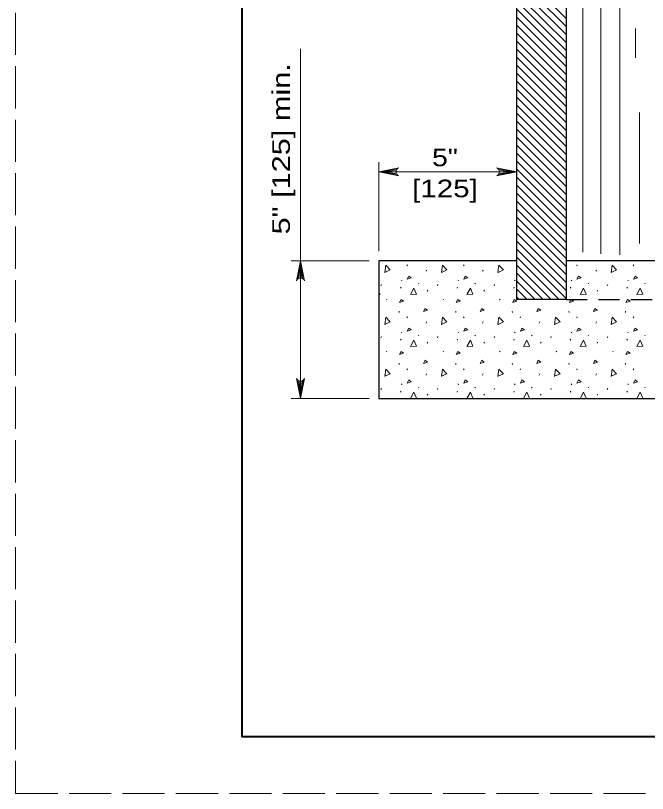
# Model space of a CAD drawing. Extents: x 1302.9 to 1336.9, y 688.5 to 710.5.
# Drawn here: x 1302.88 to 1308.46, y 688.5 to 695.37 of the extents above; entities that cross this region are included whole.
import ezdxf
from ezdxf.enums import TextEntityAlignment as Align

# ---------------------------------------------------------------- set-up
doc = ezdxf.new("R2010")
doc.units = 0
doc.header["$LTSCALE"] = 0.062
doc.linetypes.add('LONG_DASHED', pattern=[7.5, 6, -1.5])
doc.linetypes.add('MEDIUM_DASHED', pattern=[4.5, 3, -1.5])
doc.layers.add('1', color=7, linetype='Continuous', lineweight=13)

msp = doc.modelspace()

# ---------------------------------------------------------------- linework, layer by layer
at = {"layer": '1', "lineweight": 25}
for p, q in [((1307.30208, 692.86483), (1307.30208, 698.95525)), ((1312.14367, 693.20833), (1307.73933, 693.20833))]:
    msp.add_line(p, q, dxfattribs=at)
at = {"layer": '1'}
for p, q in [((1308.21275, 697.65342), (1308.21275, 693.26017)), ((1308.04517, 696.20892), (1308.04517, 693.26933)), ((1307.88642, 693.28483), (1307.88642, 696.11992)), ((1307.73933, 695.34767), (1307.30208, 695.78492)), ((1307.73933, 695.277), (1307.30208, 695.71425)), ((1307.73933, 695.20633), (1307.30208, 695.64358)), ((1307.73933, 695.13567), (1307.30208, 695.57292)), ((1307.73933, 695.065), (1307.30208, 695.50225)), ((1307.73933, 694.99433), (1307.30208, 695.43158)), ((1307.73933, 694.92358), (1307.30208, 695.36083)), ((1307.73933, 694.853), (1307.30208, 695.29025)), ((1307.73933, 694.78225), (1307.30208, 695.2195)), ((1308.3505, 694.9995), (1308.3505, 695.25892)), ((1307.73933, 694.71167), (1307.30208, 695.14892)), ((1305.39242, 691.99033), (1305.39242, 695.07867)), ((1307.73933, 694.64092), (1307.30208, 695.07817)), ((1307.73933, 694.57033), (1307.30208, 695.00758)), ((1307.73933, 694.49958), (1307.30208, 694.93683)), ((1307.73933, 694.429), (1307.30208, 694.86625)), ((1307.73933, 694.35825), (1307.30208, 694.7955)), ((1307.73933, 694.28767), (1307.30208, 694.72492)), ((1307.73933, 694.21692), (1307.30208, 694.65417)), ((1307.73933, 694.14633), (1307.30208, 694.58358)), ((1307.73933, 694.07558), (1307.30208, 694.51283)), ((1308.38742, 694.51717), (1308.38742, 693.36158)), ((1307.73933, 694.005), (1307.30208, 694.44225)), ((1307.73933, 693.93425), (1307.30208, 694.3715)), ((1307.30208, 693.5255), (1307.30208, 694.31167)), ((1307.73933, 693.86367), (1307.30208, 694.30092)), ((1307.73933, 693.79292), (1307.30208, 694.23017)), ((1307.73933, 693.72225), (1307.30208, 694.1595)), ((1306.08392, 693.29167), (1306.08392, 694.07775)), ((1307.73933, 693.65158), (1307.30208, 694.08883)), ((1306.24417, 694.01692), (1306.08392, 693.9945)), ((1306.23875, 694.00583), (1306.08392, 693.9945)), ((1307.30208, 693.9945), (1306.08392, 693.9945)), ((1306.23708, 693.9945), (1306.08392, 693.9945)), ((1306.23992, 693.98008), (1306.08392, 693.9945)), ((1306.246, 693.96967), (1306.08392, 693.9945)), ((1307.13992, 693.96967), (1307.30208, 693.9945)), ((1307.14183, 694.01692), (1307.30208, 693.9945)), ((1307.14608, 693.98008), (1307.30208, 693.9945)), ((1307.14725, 694.00583), (1307.30208, 693.9945)), ((1307.14892, 693.9945), (1307.30208, 693.9945)), ((1307.73933, 693.58092), (1307.30208, 694.01817)), ((1307.73933, 693.51025), (1307.30208, 693.9475)), ((1307.73933, 693.43958), (1307.30208, 693.87683)), ((1307.73933, 693.36892), (1307.30208, 693.80617)), ((1307.73933, 693.29825), (1307.30208, 693.7355)), ((1307.73933, 693.22758), (1307.30208, 693.66483)), ((1307.73933, 693.15692), (1307.30208, 693.59417)), ((1307.73933, 693.08625), (1307.30208, 693.5235)), ((1307.73933, 693.01558), (1307.30208, 693.45283)), ((1307.73933, 692.94492), (1307.30208, 693.38217)), ((1307.73933, 692.87425), (1307.30208, 693.3115)), ((1307.67817, 692.86483), (1307.30208, 693.24083)), ((1306.00058, 693.20833), (1305.30908, 693.20833)), ((1305.36758, 693.04625), (1305.39242, 693.20833)), ((1305.378, 693.05233), (1305.39242, 693.20833)), ((1305.39242, 693.05517), (1305.39242, 693.20833)), ((1305.40375, 693.0535), (1305.39242, 693.20833)), ((1305.41483, 693.04808), (1305.39242, 693.20833)), ((1306.33317, 693.16158), (1306.33758, 693.17158)), ((1306.833, 693.16158), (1306.83742, 693.17158)), ((1307.60742, 692.86483), (1307.30208, 693.17017)), ((1307.8325, 693.16158), (1307.83692, 693.17158)), ((1308.33225, 693.16158), (1308.33667, 693.17158)), ((1306.50175, 693.11608), (1306.50625, 693.12608)), ((1307.00158, 693.11608), (1307.00608, 693.12608)), ((1307.53683, 692.86483), (1307.30208, 693.0995)), ((1308.00108, 693.11608), (1308.00558, 693.12608)), ((1306.2845, 693.03733), (1306.289, 693.03075)), ((1306.78425, 693.03733), (1306.78875, 693.03075)), ((1307.284, 693.03733), (1307.2885, 693.03075)), ((1307.46608, 692.86483), (1307.30208, 693.02883)), ((1307.78375, 693.03733), (1307.78825, 693.03075)), ((1308.2835, 693.03733), (1308.288, 693.03075)), ((1306.10308, 692.98742), (1306.1075, 692.99742)), ((1306.27617, 692.96425), (1306.28058, 692.97425)), ((1306.434, 693.00917), (1306.43842, 693.0025)), ((1306.60283, 692.98742), (1306.60725, 692.99742)), ((1306.77592, 692.96425), (1306.78033, 692.97425)), ((1306.93375, 693.00917), (1306.93817, 693.0025)), ((1307.10258, 692.98742), (1307.107, 692.99742)), ((1307.27567, 692.96425), (1307.28008, 692.97425)), ((1307.39533, 692.86483), (1307.30208, 692.95808)), ((1307.77542, 692.96425), (1307.77983, 692.97425)), ((1307.93325, 693.00917), (1307.93767, 693.0025)), ((1308.10208, 692.98742), (1308.1065, 692.99742)), ((1308.27517, 692.96425), (1308.27958, 692.97425)), ((1308.43308, 693.00917), (1308.43742, 693.0025)), ((1306.09525, 692.90842), (1306.08392, 692.91)), ((1306.51292, 692.93875), (1306.51733, 692.94867)), ((1307.01275, 692.93875), (1307.01717, 692.94867)), ((1307.32475, 692.86483), (1307.30208, 692.8875)), ((1308.01225, 692.93875), (1308.01667, 692.94867)), ((1306.15183, 692.86775), (1306.15625, 692.86108)), ((1306.65167, 692.86775), (1306.65608, 692.86108)), ((1307.15142, 692.86775), (1307.15583, 692.86108)), ((1308.15092, 692.86775), (1308.15533, 692.86108)), ((1306.264, 692.76125), (1306.26517, 692.75125)), ((1306.76375, 692.76125), (1306.76492, 692.75125)), ((1307.2635, 692.76125), (1307.26467, 692.75125)), ((1307.76325, 692.76125), (1307.76442, 692.75125)), ((1308.263, 692.76125), (1308.26417, 692.75125)), ((1306.33317, 692.70242), (1306.33758, 692.71242)), ((1306.833, 692.70242), (1306.83742, 692.71242)), ((1307.33275, 692.70242), (1307.33717, 692.71242)), ((1307.8325, 692.70242), (1307.83692, 692.71242)), ((1308.33225, 692.70242), (1308.33667, 692.71242)), ((1306.50175, 692.65692), (1306.50625, 692.66692)), ((1307.00158, 692.65692), (1307.00608, 692.66692)), ((1307.50133, 692.65692), (1307.50583, 692.66692)), ((1308.00108, 692.65692), (1308.00558, 692.66692)), ((1306.10308, 692.52825), (1306.1075, 692.53825)), ((1306.2845, 692.57825), (1306.289, 692.57158)), ((1306.434, 692.55), (1306.43842, 692.54333)), ((1306.60283, 692.52825), (1306.60725, 692.53825)), ((1306.78425, 692.57825), (1306.78875, 692.57158)), ((1306.93375, 692.55), (1306.93817, 692.54333)), ((1307.10258, 692.52825), (1307.107, 692.53825)), ((1307.284, 692.57825), (1307.2885, 692.57158)), ((1307.4335, 692.55), (1307.43792, 692.54333)), ((1307.60233, 692.52825), (1307.60675, 692.53825)), ((1307.78375, 692.57825), (1307.78825, 692.57158)), ((1307.93325, 692.55), (1307.93767, 692.54333)), ((1308.10208, 692.52825), (1308.1065, 692.53825)), ((1308.2835, 692.57825), (1308.288, 692.57158)), ((1308.43308, 692.55), (1308.43742, 692.54333)), ((1306.27617, 692.50508), (1306.28058, 692.51508)), ((1306.51292, 692.47958), (1306.51733, 692.4895)), ((1306.77592, 692.50508), (1306.78033, 692.51508)), ((1307.01275, 692.47958), (1307.01717, 692.4895)), ((1307.27567, 692.50508), (1307.28008, 692.51508)), ((1307.5125, 692.47958), (1307.51692, 692.4895)), ((1307.77542, 692.50508), (1307.77983, 692.51508)), ((1308.01225, 692.47958), (1308.01667, 692.4895)), ((1308.27517, 692.50508), (1308.27958, 692.51508)), ((1306.15183, 692.40858), (1306.15625, 692.40192)), ((1306.65167, 692.40858), (1306.65608, 692.40192)), ((1307.15142, 692.40858), (1307.15583, 692.40192)), ((1307.65117, 692.40858), (1307.65558, 692.40192)), ((1308.15092, 692.40858), (1308.15533, 692.40192)), ((1306.264, 692.30217), (1306.26517, 692.29217)), ((1306.76375, 692.30217), (1306.76492, 692.29217)), ((1307.2635, 692.30217), (1307.26467, 692.29217)), ((1307.76325, 692.30217), (1307.76442, 692.29217)), ((1308.263, 692.30217), (1308.26417, 692.29217)), ((1306.33317, 692.24325), (1306.33758, 692.25325)), ((1306.50175, 692.19775), (1306.50625, 692.20775)), ((1306.833, 692.24325), (1306.83742, 692.25325)), ((1307.00158, 692.19775), (1307.00608, 692.20775)), ((1307.33275, 692.24325), (1307.33717, 692.25325)), ((1307.50133, 692.19775), (1307.50583, 692.20775)), ((1307.8325, 692.24325), (1307.83692, 692.25325)), ((1308.00108, 692.19775), (1308.00558, 692.20775)), ((1308.33225, 692.24325), (1308.33667, 692.25325)), ((1305.37, 692.15058), (1305.39242, 691.99033)), ((1305.38108, 692.14508), (1305.39242, 691.99033)), ((1305.41717, 692.15242), (1305.39242, 691.99033)), ((1305.40675, 692.14633), (1305.39242, 691.99033)), ((1305.39242, 692.1435), (1305.39242, 691.99033)), ((1306.10308, 692.06908), (1306.1075, 692.07908)), ((1306.2845, 692.11908), (1306.289, 692.11242)), ((1306.434, 692.09083), (1306.43842, 692.08417)), ((1306.60283, 692.06908), (1306.60725, 692.07908)), ((1306.78425, 692.11908), (1306.78875, 692.11242)), ((1306.93375, 692.09083), (1306.93817, 692.08417)), ((1307.10258, 692.06908), (1307.107, 692.07908)), ((1307.284, 692.11908), (1307.2885, 692.11242)), ((1307.4335, 692.09083), (1307.43792, 692.08417)), ((1307.60233, 692.06908), (1307.60675, 692.07908)), ((1307.78375, 692.11908), (1307.78825, 692.11242)), ((1307.93325, 692.09083), (1307.93767, 692.08417)), ((1308.10208, 692.06908), (1308.1065, 692.07908)), ((1308.2835, 692.11908), (1308.288, 692.11242)), ((1308.43308, 692.09083), (1308.43742, 692.08417)), ((1306.00058, 691.99033), (1305.30908, 691.99033)), ((1306.27617, 692.04592), (1306.28058, 692.05592)), ((1306.51292, 692.02042), (1306.51733, 692.03033)), ((1306.77592, 692.04592), (1306.78033, 692.05592)), ((1307.01275, 692.02042), (1307.01717, 692.03033)), ((1307.27567, 692.04592), (1307.28008, 692.05592)), ((1307.5125, 692.02042), (1307.51692, 692.03033)), ((1307.77542, 692.04592), (1307.77983, 692.05592)), ((1308.01225, 692.02042), (1308.01667, 692.03033)), ((1308.27517, 692.04592), (1308.27958, 692.05592))]:
    msp.add_line(p, q, dxfattribs=at)
at = {"layer": '1', "linetype": 'MEDIUM_DASHED', "lineweight": 25}
msp.add_line((1307.73933, 692.86483), (1312.14367, 692.86483), dxfattribs=at)
at = {"layer": '1', "linetype": 'LONG_DASHED'}
msp.add_lwpolyline([(1302.8765, 688.50158), (1336.8765, 688.50158), (1336.8765, 710.50158), (1302.8765, 710.50158)], close=True, dxfattribs=at)
at = {"layer": '1', "lineweight": 25}
for points in [[(1336.3765, 689.00158), (1304.8765, 689.00158), (1304.8765, 710.00158)], [(1307.73933, 700.04825), (1307.73933, 692.86483), (1307.30208, 692.86483)], [(1306.08392, 691.99033), (1313.799, 691.99033), (1313.799, 693.20833), (1312.58092, 693.20833)], [(1307.30208, 693.20833), (1306.08392, 693.20833), (1306.08392, 691.99033)]]:
    msp.add_lwpolyline(points, dxfattribs=at)
at = {"layer": '1', "lineweight": 40}
msp.add_lwpolyline([(1304.8765, 710.00158), (1336.3765, 710.00158), (1336.3765, 689.00158), (1304.8765, 689.00158)], close=True, dxfattribs=at)
msp.add_lwpolyline([(1304.8765, 710.00158), (1336.3765, 710.00158), (1336.3765, 689.00158), (1304.8765, 689.00158)], close=True, dxfattribs=at)
at = {"layer": '1'}
for points in [[(1306.26092, 693.95908), (1306.08392, 693.9945), (1306.26092, 694.02992)], [(1307.12508, 693.95908), (1307.30208, 693.9945), (1307.12508, 694.02992)], [(1305.357, 693.03133), (1305.39242, 693.20833), (1305.42783, 693.03133)], [(1306.137, 693.10458), (1306.14583, 693.16808), (1306.18558, 693.127), (1306.13808, 693.105)], [(1306.63683, 693.10458), (1306.64567, 693.16808), (1306.68533, 693.127), (1306.63783, 693.105)], [(1307.13658, 693.10458), (1307.14542, 693.16808), (1307.18517, 693.127), (1307.13758, 693.105)], [(1308.13608, 693.10458), (1308.14492, 693.16808), (1308.18467, 693.127), (1308.13708, 693.105)], [(1306.36308, 692.90875), (1306.39308, 692.96533), (1306.41642, 692.91317), (1306.36425, 692.90875)], [(1306.86283, 692.90875), (1306.89283, 692.96533), (1306.91617, 692.91317), (1306.864, 692.90875)], [(1307.86242, 692.90875), (1307.89242, 692.96533), (1307.91567, 692.91317), (1307.86358, 692.90875)], [(1308.36217, 692.90875), (1308.39217, 692.96533), (1308.4155, 692.91317), (1308.36333, 692.90875)], [(1306.08392, 692.92558), (1306.08625, 692.92783), (1306.09508, 692.90883)], [(1306.137, 692.64542), (1306.14583, 692.70892), (1306.18558, 692.66783), (1306.13808, 692.64583)], [(1306.63683, 692.64542), (1306.64567, 692.70892), (1306.68533, 692.66783), (1306.63783, 692.64583)], [(1307.13658, 692.64542), (1307.14542, 692.70892), (1307.18517, 692.66783), (1307.13758, 692.64583)], [(1307.63633, 692.64542), (1307.64517, 692.70892), (1307.68492, 692.66783), (1307.63733, 692.64583)], [(1308.13608, 692.64542), (1308.14492, 692.70892), (1308.18467, 692.66783), (1308.13708, 692.64583)], [(1306.36308, 692.44967), (1306.39308, 692.50617), (1306.41642, 692.454), (1306.36425, 692.44967)], [(1306.86283, 692.44967), (1306.89283, 692.50617), (1306.91617, 692.454), (1306.864, 692.44967)], [(1307.36267, 692.44967), (1307.39258, 692.50617), (1307.41592, 692.454), (1307.36383, 692.44967)], [(1307.86242, 692.44967), (1307.89242, 692.50617), (1307.91567, 692.454), (1307.86358, 692.44967)], [(1308.36217, 692.44967), (1308.39217, 692.50617), (1308.4155, 692.454), (1308.36333, 692.44967)], [(1306.137, 692.18625), (1306.14583, 692.24975), (1306.18558, 692.20867), (1306.13808, 692.18667)], [(1306.63683, 692.18625), (1306.64567, 692.24975), (1306.68533, 692.20867), (1306.63783, 692.18667)], [(1307.13658, 692.18625), (1307.14542, 692.24975), (1307.18517, 692.20867), (1307.13758, 692.18667)], [(1307.63633, 692.18625), (1307.64517, 692.24975), (1307.68492, 692.20867), (1307.63733, 692.18667)], [(1308.13608, 692.18625), (1308.14492, 692.24975), (1308.18467, 692.20867), (1308.13708, 692.18667)], [(1305.42783, 692.16733), (1305.39242, 691.99033), (1305.357, 692.16733)], [(1306.36308, 691.9905), (1306.39308, 692.047), (1306.41642, 691.99492), (1306.36425, 691.9905)], [(1306.86283, 691.9905), (1306.89283, 692.047), (1306.91617, 691.99492), (1306.864, 691.9905)], [(1307.36267, 691.9905), (1307.39258, 692.047), (1307.41592, 691.99492), (1307.36383, 691.9905)], [(1307.86242, 691.9905), (1307.89242, 692.047), (1307.91567, 691.99492), (1307.86358, 691.9905)], [(1308.36217, 691.9905), (1308.39217, 692.047), (1308.4155, 691.99492), (1308.36333, 691.9905)]]:
    msp.add_lwpolyline(points, dxfattribs=at)
for points in [[(1306.33533, 693.04508), (1306.34867, 693.07283), (1306.37092, 693.05617)], [(1306.83517, 693.04508), (1306.84842, 693.07283), (1306.87067, 693.05617)], [(1307.83467, 693.04508), (1307.848, 693.07283), (1307.87025, 693.05617)], [(1308.33442, 693.04508), (1308.34775, 693.07283), (1308.37, 693.05617)], [(1306.26833, 692.83892), (1306.28167, 692.86667), (1306.30392, 692.85)], [(1306.76808, 692.83892), (1306.78142, 692.86667), (1306.80367, 692.85)], [(1307.26783, 692.83892), (1307.28117, 692.86667), (1307.30342, 692.85)], [(1307.76758, 692.83892), (1307.78092, 692.86667), (1307.80317, 692.85)], [(1308.26733, 692.83892), (1308.28067, 692.86667), (1308.30292, 692.85)], [(1306.47992, 692.7595), (1306.49317, 692.78733), (1306.51533, 692.77067)], [(1306.97967, 692.7595), (1306.993, 692.78733), (1307.01517, 692.77067)], [(1307.47942, 692.7595), (1307.49275, 692.78733), (1307.51492, 692.77067)], [(1307.97917, 692.7595), (1307.9925, 692.78733), (1308.01467, 692.77067)], [(1306.33533, 692.586), (1306.34867, 692.61367), (1306.37092, 692.597)], [(1306.83517, 692.586), (1306.84842, 692.61367), (1306.87067, 692.597)], [(1307.33492, 692.586), (1307.34825, 692.61367), (1307.3705, 692.597)], [(1307.83467, 692.586), (1307.848, 692.61367), (1307.87025, 692.597)], [(1308.33442, 692.586), (1308.34775, 692.61367), (1308.37, 692.597)], [(1306.26833, 692.37975), (1306.28167, 692.4075), (1306.30392, 692.39083)], [(1306.76808, 692.37975), (1306.78142, 692.4075), (1306.80367, 692.39083)], [(1307.26783, 692.37975), (1307.28117, 692.4075), (1307.30342, 692.39083)], [(1307.76758, 692.37975), (1307.78092, 692.4075), (1307.80317, 692.39083)], [(1308.26733, 692.37975), (1308.28067, 692.4075), (1308.30292, 692.39083)], [(1306.47992, 692.3005), (1306.49317, 692.32817), (1306.51533, 692.3115)], [(1306.97967, 692.3005), (1306.993, 692.32817), (1307.01517, 692.3115)], [(1307.47942, 692.3005), (1307.49275, 692.32817), (1307.51492, 692.3115)], [(1307.97917, 692.3005), (1307.9925, 692.32817), (1308.01467, 692.3115)], [(1306.33533, 692.12683), (1306.34867, 692.15458), (1306.37092, 692.13792)], [(1306.83517, 692.12683), (1306.84842, 692.15458), (1306.87067, 692.13792)], [(1307.33492, 692.12683), (1307.34825, 692.15458), (1307.3705, 692.13792)], [(1307.83467, 692.12683), (1307.848, 692.15458), (1307.87025, 692.13792)], [(1308.33442, 692.12683), (1308.34775, 692.15458), (1308.37, 692.13792)]]:
    msp.add_lwpolyline(points, close=True, dxfattribs=at)
for centre, start, end in [((1306.27519, 693.99453), 112.08782, 247.91395), ((1307.11078, 693.99453), 292.08605, 67.91218), ((1305.39243, 693.01706), 22.08782, 157.91395), ((1305.39235, 692.1816), 202.08782, 337.91395)]:
    msp.add_arc(centre, 0.0382, start, end, dxfattribs=at)

# ---------------------------------------------------------------- texts
at = {"layer": '1', "width": 1.3}
msp.add_text('5" [125] min.', height=0.156, rotation=90, dxfattribs=at).set_placement((1305.29933, 694.19683), align=Align.CENTER)
at = {"layer": '1'}
for s, width, p in [('5"', 1.2, (1306.66871, 694.04275)), ('[125]', 1.25, (1306.66867, 693.76875))]:
    msp.add_text(s, height=0.156, dxfattribs=dict(at, width=width)).set_placement(p, align=Align.CENTER)

doc.saveas('drawing.dxf')
